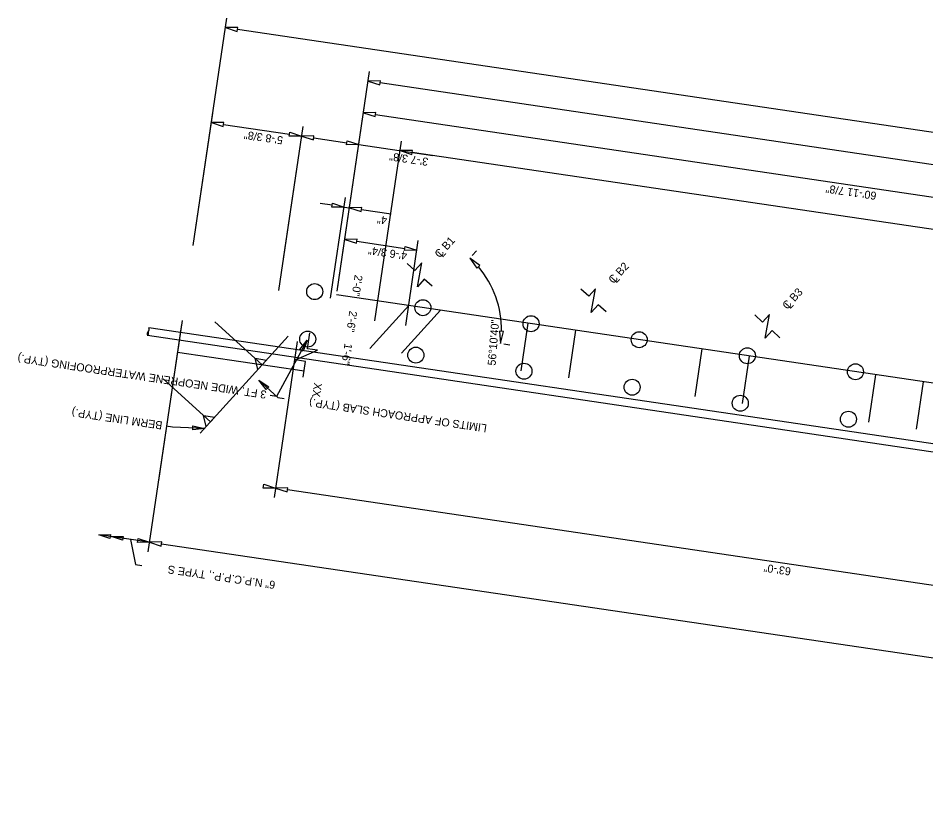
# Model space of a CAD drawing. Extents: x 1467956 to 1469946, y 573734 to 574139.
# Drawn here: x 1468952.5 to 1469009.2, y 573995.3 to 574044.2 of the extents above; entities that cross this region are included whole.
import ezdxf

# ---------------------------------------------------------------- set-up
doc = ezdxf.new("R2010")
doc.units = 0
for name, color, linetype in [('BR_P_Dia_Hidden', 7, 'Continuous'), ('BR_P_Gen_NonPerf_Pipe', 7, 'Continuous'), ('BR_P_Gen_Text', 7, 'Continuous'), ('BR_P_Sub_Deep_Hidden', 7, 'Continuous'), ('BR_P_Sub_Hidden', 7, 'Continuous'), ('BR_P_Sub_Text', 7, 'Continuous'), ('Default', 7, 'Continuous')]:
    doc.layers.add(name, color=color, linetype=linetype)

# ---------------------------------------------------------------- blocks, each defined once
blk = doc.blocks.new('arrowOhio')
at = {"layer": 'Default'}
blk.add_lwpolyline([(0.00381, 0.000635), (0.00381, -0.000635), (0, 0)], close=True, dxfattribs=at)

msp = doc.modelspace()

# ---------------------------------------------------------------- linework, layer by layer
at = {"layer": 'BR_P_Dia_Hidden'}
for p, q in [((1469066.452, 574013.016), (1468972.385, 574026.942)), ((1468984.344, 574025.171), (1468983.905, 574022.204)), ((1468987.312, 574024.732), (1468986.873, 574021.764)), ((1468995.21, 574023.563), (1468994.77, 574020.595)), ((1468998.177, 574023.123), (1468997.738, 574020.156)), ((1469006.075, 574021.954), (1469005.636, 574018.987)), ((1469009.043, 574021.515), (1469008.603, 574018.547))]:
    msp.add_line(p, q, dxfattribs=at)
at = {"layer": 'BR_P_Gen_NonPerf_Pipe'}
for p, q in [((1469074.927, 574007.97), (1468960.648, 574024.889)), ((1469074.854, 574007.475), (1468960.574, 574024.394))]:
    msp.add_line(p, q, dxfattribs=at)
for centre, start, end in [((1468960.5, 574024.784), 307.976, 35.1816), ((1468960.723, 574024.498), 127.976, 215.1816), ((1468960.463, 574024.537), 307.976, 35.1816)]:
    msp.add_arc(centre, 0.181, start, end, dxfattribs=at)
at = {"layer": 'BR_P_Gen_Text'}
for p, q in [((1468963.43, 574030.027), (1468965.533, 574044.232)), ((1469075.016, 574027.417), (1468966.197, 574043.527)), ((1468972.42, 574027.179), (1468974.45, 574040.89)), ((1469067.677, 574026.481), (1468975.114, 574040.185)), ((1468972.42, 574027.179), (1468974.157, 574038.911)), ((1468963.43, 574030.027), (1468964.654, 574038.296)), ((1468974.821, 574038.207), (1469033.645, 574029.498)), ((1468965.318, 574037.592), (1468969.451, 574036.98)), ((1468968.774, 574027.214), (1468970.291, 574037.462)), ((1468969.067, 574029.192), (1468970.291, 574037.462)), ((1468972.42, 574027.179), (1468973.864, 574036.933)), ((1468970.955, 574036.757), (1468973.024, 574036.451)), ((1468973.776, 574036.339), (1468978.394, 574035.656)), ((1468972.015, 574026.734), (1468972.947, 574033.025)), ((1468972.42, 574027.179), (1468973.278, 574032.976)), ((1468972.107, 574032.543), (1468971.355, 574032.654)), ((1468972.859, 574032.432), (1468973.19, 574032.383)), ((1468973.942, 574032.271), (1468975.803, 574031.996)), ((1468972.42, 574027.179), (1468972.985, 574030.998)), ((1468973.649, 574030.293), (1468976.655, 574029.848)), ((1468976.71, 574025.028), (1468977.495, 574030.33)), ((1468980.87, 574029.41), (1468981.121, 574029.686)), ((1468962.701, 574025.1), (1468961.257, 574015.347)), ((1468969.922, 574024.031), (1468968.478, 574014.278)), ((1468969.922, 574024.031), (1468968.478, 574014.278)), ((1468970.541, 574024.119), (1468968.638, 574020.601)), ((1468982.848, 574023.877), (1468983.217, 574023.822)), ((1468967.537, 574021.604), (1468968.721, 574020.528)), ((1468968.638, 574020.601), (1468968.242, 574020.66)), ((1468968.721, 574020.528), (1468969.117, 574020.469)), ((1468962.136, 574018.679), (1468961.74, 574018.737)), ((1468964.134, 574018.6), (1468962.136, 574018.679)), ((1469030.13, 574005.757), (1468969.318, 574014.76))]:
    msp.add_line(p, q, dxfattribs=at)
for points in [[(1468966.179, 574043.402), (1468966.216, 574043.652), (1468965.445, 574043.638)], [(1468975.095, 574040.06), (1468975.132, 574040.31), (1468974.362, 574040.296)], [(1468974.802, 574038.081), (1468974.839, 574038.332), (1468974.069, 574038.318)], [(1468965.3, 574037.466), (1468965.337, 574037.717), (1468964.567, 574037.703)], [(1468969.433, 574036.854), (1468969.47, 574037.105), (1468970.203, 574036.868)], [(1468970.936, 574036.632), (1468970.973, 574036.882), (1468970.203, 574036.868)], [(1468973.006, 574036.325), (1468973.043, 574036.576), (1468973.776, 574036.339)], [(1468972.088, 574032.418), (1468972.126, 574032.668), (1468972.859, 574032.432)], [(1468973.923, 574032.146), (1468973.961, 574032.397), (1468973.19, 574032.383)], [(1468973.631, 574030.168), (1468973.668, 574030.418), (1468972.897, 574030.404)], [(1468976.637, 574029.723), (1468976.674, 574029.973), (1468977.407, 574029.737)], [(1468981.156, 574028.608), (1468981.338, 574028.785), (1468980.718, 574029.242)], [(1468982.813, 574024.657), (1468982.561, 574024.678), (1468982.623, 574023.91)], [(1468967.795, 574014.857), (1468967.832, 574015.108), (1468968.566, 574014.871)], [(1468969.299, 574014.634), (1468969.336, 574014.885), (1468968.566, 574014.871)]]:
    msp.add_lwpolyline(points, close=True, dxfattribs=at)
for points in [[(1468978.361, 574027.482), (1468977.871, 574027.926), (1468977.441, 574027.453), (1468977.709, 574028.938), (1468977.279, 574028.464), (1468976.79, 574028.909)], [(1468989.226, 574025.873), (1468988.737, 574026.318), (1468988.307, 574025.844), (1468988.575, 574027.329), (1468988.145, 574026.856), (1468987.655, 574027.3)], [(1469000.092, 574024.265), (1468999.602, 574024.709), (1468999.172, 574024.235), (1468999.44, 574025.721), (1468999.01, 574025.247), (1468998.52, 574025.692)], [(1468970.298, 574021.792), (1468970.445, 574022.781), (1468969.812, 574022.875), (1468971.195, 574023.479), (1468970.562, 574023.573), (1468970.708, 574024.562)]]:
    msp.add_lwpolyline(points, dxfattribs=at)
msp.add_arc((1468976.675, 574024.79), 6.013, 358.825, 40.5103, dxfattribs=at)
at = {"layer": 'BR_P_Sub_Deep_Hidden'}
for centre in [(1468971.019, 574027.144), (1468977.779, 574026.143), (1468984.539, 574025.143), (1468970.58, 574024.176), (1468991.298, 574024.142), (1468977.34, 574023.176), (1468998.058, 574023.141), (1468984.099, 574022.175), (1469004.817, 574022.14), (1468990.859, 574021.174), (1468997.618, 574020.173), (1469004.378, 574019.173)]:
    msp.add_circle(centre, 0.5, dxfattribs=at)
at = {"layer": 'BR_P_Sub_Hidden'}
for p, q in [((1468974.472, 574023.6), (1468976.9, 574026.274)), ((1468976.45, 574023.307), (1468978.878, 574025.981))]:
    msp.add_line(p, q, dxfattribs=at)
at = {"layer": 'BR_P_Sub_Text'}
for p, q in [((1468974.778, 574025.314), (1468976.442, 574036.551)), ((1469062.525, 574023.201), (1468977.106, 574035.847)), ((1468962.736, 574025.338), (1468962.443, 574023.359)), ((1468967.743, 574022.575), (1468964.782, 574025.264)), ((1468969.362, 574024.357), (1468963.859, 574018.297)), ((1468962.466, 574023.518), (1468960.598, 574010.895)), ((1468962.443, 574023.359), (1468970.357, 574022.188)), ((1468964.506, 574019.01), (1468961.545, 574021.699)), ((1468960.686, 574011.489), (1468957.52, 574011.957)), ((1468959.499, 574011.664), (1468959.82, 574010.097)), ((1469070.257, 573995.267), (1468961.437, 574011.377)), ((1468959.82, 574010.097), (1468960.215, 574010.038))]:
    msp.add_line(p, q, dxfattribs=at)
for points in [[(1468977.087, 574035.721), (1468977.124, 574035.972), (1468976.354, 574035.958)], [(1468967.474, 574022.278), (1468967.299, 574022.978), (1468968.012, 574022.871)], [(1468964.237, 574018.714), (1468964.062, 574019.414), (1468964.775, 574019.306)], [(1468961.419, 574011.252), (1468961.456, 574011.503), (1468960.686, 574011.489)]]:
    msp.add_lwpolyline(points, close=True, dxfattribs=at)

# ---------------------------------------------------------------- block references
at = {"layer": 'BR_P_Gen_Text'}
for p, xscale, yscale, rotation in [((1468970.541, 574024.119), 191.49568, 191.49568, -118.42123067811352), ((1468967.537, 574021.604), 191.49568, 191.49568, -42.243452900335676), ((1468964.134, 574018.6), 191.49568000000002, 191.49568000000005, 177.75654709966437)]:
    msp.add_blockref('arrowOhio', p, dxfattribs=dict(at, xscale=xscale, yscale=yscale, rotation=rotation))
at = {"layer": 'BR_P_Sub_Text', "xscale": 191.49568000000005, "yscale": 191.49568}
for p, rotation in [((1468957.52, 574011.957), -8.421230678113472), ((1468958.312, 574011.84), -8.421230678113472), ((1468960.686, 574011.489), 171.57876932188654)]:
    msp.add_blockref('arrowOhio', p, dxfattribs=dict(at, rotation=rotation))

# ---------------------------------------------------------------- texts
at = {"layer": 'BR_P_Gen_Text'}
for s, rotation, p in [('5\'-8 3/8"', 171.5788, (1468969.064, 574036.835)), ('3\'-7 3/8"', 171.5788, (1468978.147, 574035.49)), ('60\'-11 7/8"', 171.5788, (1469006.155, 574033.365)), ('4"', 171.5788, (1468975.569, 574031.828)), ('C B1', 47.7565, (1468978.831, 574029.206)), ('4\'-6 3/4"', 171.5788, (1468976.827, 574029.62)), ('L', 47.7565, (1468979.006, 574029.25)), ('C B2', 47.7565, (1468989.696, 574027.598)), ('2\'-0"', 261.5788, (1468973.524, 574028.219)), ('L', 47.7565, (1468989.871, 574027.641)), ('C B3', 47.7565, (1469000.562, 574025.989)), ('L', 47.7565, (1469000.737, 574026.033)), ('2\'-6"', 261.5788, (1468973.191, 574025.973)), ('56°10\'40"', 85.3928, (1468982.323, 574022.51)), ('1\'-6"', 261.5788, (1468972.89, 574023.938)), ('3 FT. WIDE NEOPRENE WATERPROOFING (TYP.)', 171.5788, (1468968.031, 574020.944)), ('XX', 261.5788, (1468970.985, 574021.475)), ('LIMITS OF APPROACH SLAB (TYP.)', 171.5788, (1468981.807, 574018.843)), ('BERM LINE (TYP.)', 171.5788, (1468961.529, 574019.021)), ('6" N.P.C.P.P., TYPE S', 171.5788, (1468968.584, 574009.052)), ('63\'-0"', 171.5788, (1469000.809, 574009.895))]:
    msp.add_text(s, height=0.5, rotation=rotation, dxfattribs=at).set_placement(p)

doc.saveas('drawing.dxf')
